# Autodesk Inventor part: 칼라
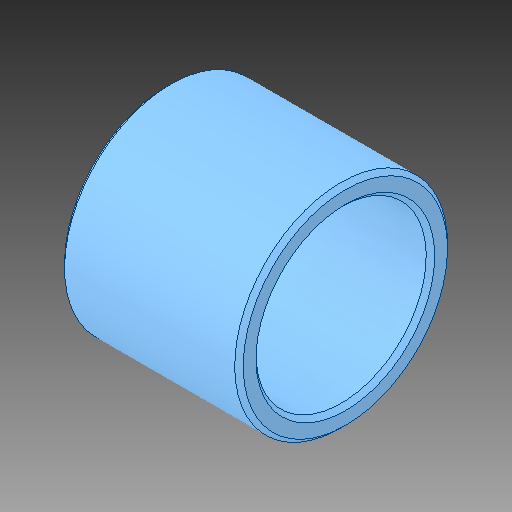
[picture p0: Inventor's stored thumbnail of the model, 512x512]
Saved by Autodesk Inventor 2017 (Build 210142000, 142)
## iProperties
Created: 2024-08
Part Number: 칼라
Material: 일반
Document SubType Name: Modeling
Designer: MRC
Density: 1 g/cm^3
Appearance: 기본값
Author: jhkim
Sending System: Autodesk Inventor 2025
Preprocessor: ST-DEVELOPER v20
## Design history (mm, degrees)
feature "솔리드1"
node "솔리드2"
